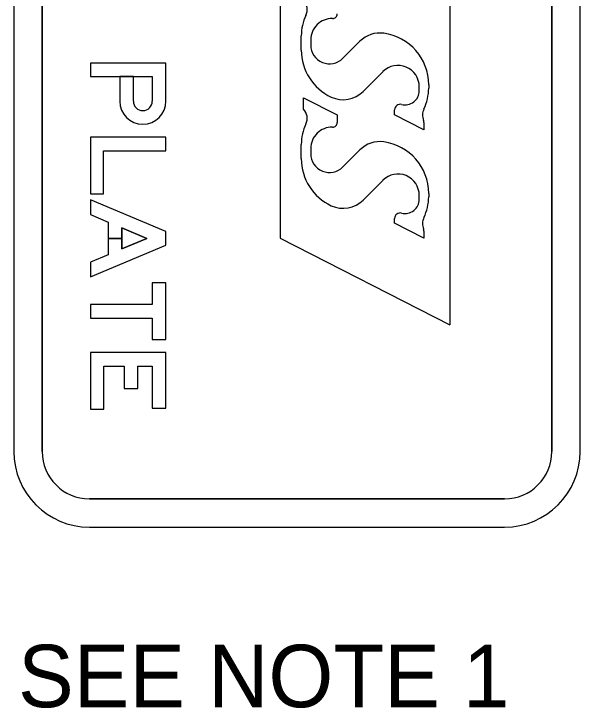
# Model space of a CAD drawing. Extents: x 46672 to 47298, y 5424 to 5829.
# Drawn here: x 46903.28 to 46928.7, y 5543.9 to 5575.02 of the extents above; entities that cross this region are included whole.
import ezdxf

# ---------------------------------------------------------------- set-up
doc = ezdxf.new("R2010")
doc.units = 0
doc.layers.add('SignPanel', color=7, linetype='Continuous')
doc.layers.add('TextLabel', color=7, linetype='Continuous')

msp = doc.modelspace()

# ---------------------------------------------------------------- linework, layer by layer
at = {"layer": 'SignPanel'}
for p, q in [((46903.285, 5609.609), (46903.285, 5555.399)), ((46903.285, 5609.609), (46903.285, 5555.399)), ((46903.285, 5609.596), (46903.285, 5555.399)), ((46903.285, 5609.596), (46903.285, 5555.399)), ((46904.555, 5609.609), (46904.555, 5555.399)), ((46904.555, 5555.399), (46904.555, 5609.596)), ((46904.555, 5555.399), (46904.555, 5609.596)), ((46927.425, 5555.399), (46927.425, 5609.609)), ((46927.425, 5609.609), (46927.425, 5555.399)), ((46927.425, 5609.609), (46927.425, 5555.399)), ((46928.696, 5555.399), (46928.696, 5609.609)), ((46928.696, 5555.399), (46928.696, 5609.609)), ((46928.696, 5555.399), (46928.696, 5609.609)), ((46928.696, 5555.399), (46928.696, 5609.609)), ((46915.23, 5585.803), (46915.23, 5564.971)), ((46922.852, 5585.242), (46922.852, 5561.087)), ((46916.183, 5573.4), (46916.183, 5574.037)), ((46916.606, 5573.857), (46916.606, 5573.628)), ((46918.052, 5573.03), (46918.814, 5573.791)), ((46919.85, 5572.431), (46918.962, 5571.544)), ((46908.038, 5572.208), (46908.038, 5571.107)), ((46909.495, 5572.208), (46909.495, 5571.107)), ((46909.495, 5572.208), (46909.495, 5571.107)), ((46909.495, 5572.208), (46909.495, 5571.107)), ((46921.475, 5571.576), (46921.475, 5571.757)), ((46921.899, 5571.844), (46921.899, 5571.684)), ((46916.289, 5571.26), (46917.798, 5570.492)), ((46916.289, 5570.745), (46916.289, 5571.26)), ((46920.366, 5570.502), (46920.366, 5570.714)), ((46917.798, 5570.492), (46917.798, 5570.151)), ((46921.687, 5569.829), (46920.366, 5570.502)), ((46921.687, 5570.147), (46921.687, 5569.829)), ((46916.183, 5568.531), (46916.183, 5569.169)), ((46916.606, 5568.988), (46916.606, 5568.759)), ((46918.052, 5568.16), (46918.814, 5568.922)), ((46919.85, 5567.561), (46918.962, 5566.674)), ((46921.899, 5566.974), (46921.899, 5566.814)), ((46921.475, 5566.707), (46921.475, 5566.888)), ((46920.366, 5565.633), (46920.366, 5565.845)), ((46921.687, 5564.96), (46920.366, 5565.633)), ((46921.687, 5565.278), (46921.687, 5564.96)), ((46915.23, 5564.971), (46922.852, 5561.087)), ((46906.673, 5553.282), (46925.307, 5553.282)), ((46925.307, 5553.282), (46906.673, 5553.282)), ((46925.307, 5553.282), (46906.673, 5553.282)), ((46906.673, 5552.011), (46925.307, 5552.011)), ((46906.673, 5552.011), (46925.307, 5552.011)), ((46906.673, 5552.011), (46925.307, 5552.011)), ((46906.673, 5552.011), (46925.307, 5552.011))]:
    msp.add_line(p, q, dxfattribs=at)
for points in [[(46910.105, 5571.107), (46910.105, 5572.818), (46906.717, 5572.818), (46906.717, 5572.208), (46908.038, 5572.208)], [(46910.105, 5571.107), (46910.105, 5572.818), (46906.717, 5572.818), (46906.717, 5572.208), (46909.495, 5572.208)], [(46910.105, 5571.107), (46910.105, 5572.818), (46906.717, 5572.818), (46906.717, 5572.208), (46909.495, 5572.208)], [(46908.648, 5571.107), (46908.648, 5572.208), (46908.038, 5572.208), (46908.038, 5571.107)], [(46908.648, 5571.107), (46908.648, 5572.208), (46908.038, 5572.208), (46908.038, 5571.107)], [(46908.648, 5571.107), (46908.648, 5572.208), (46909.495, 5572.208)]]:
    msp.add_lwpolyline(points, dxfattribs=at)
for points in [[(46906.717, 5566.956), (46907.309, 5566.956), (46907.309, 5568.887), (46910.105, 5568.887), (46910.105, 5569.497), (46906.717, 5569.497)], [(46906.717, 5566.956), (46907.309, 5566.956), (46907.309, 5568.887), (46910.105, 5568.887), (46910.105, 5569.497), (46906.717, 5569.497)], [(46906.717, 5566.956), (46907.309, 5566.956), (46907.309, 5568.887), (46910.105, 5568.887), (46910.105, 5569.497), (46906.717, 5569.497)], [(46907.513, 5565.689), (46907.513, 5564.225), (46906.717, 5563.891), (46906.717, 5563.229), (46910.105, 5564.652), (46910.105, 5565.262), (46906.717, 5566.685), (46906.717, 5566.024)], [(46908.123, 5564.481), (46908.123, 5564.957), (46907.513, 5564.957), (46907.513, 5564.225), (46906.717, 5563.891), (46906.717, 5563.229), (46910.105, 5564.652), (46910.105, 5565.262), (46906.717, 5566.685), (46906.717, 5566.024), (46907.513, 5565.689), (46907.513, 5564.957), (46908.123, 5564.957), (46908.123, 5565.433), (46909.256, 5564.957)], [(46908.123, 5564.481), (46908.123, 5564.957), (46907.513, 5564.957), (46907.513, 5564.225), (46906.717, 5563.891), (46906.717, 5563.229), (46910.105, 5564.652), (46910.105, 5565.262), (46906.717, 5566.685), (46906.717, 5566.024), (46907.513, 5565.689), (46907.513, 5564.957), (46908.123, 5564.957), (46908.123, 5565.433), (46909.256, 5564.957)], [(46908.123, 5564.481), (46909.256, 5564.957), (46908.123, 5565.433)], [(46909.495, 5562.958), (46909.495, 5561.993), (46906.717, 5561.993), (46906.717, 5561.383), (46909.495, 5561.383), (46909.495, 5560.417), (46910.105, 5560.417), (46910.105, 5562.958)], [(46909.495, 5562.958), (46909.495, 5561.993), (46906.717, 5561.993), (46906.717, 5561.383), (46909.495, 5561.383), (46909.495, 5560.417), (46910.105, 5560.417), (46910.105, 5562.958)], [(46909.495, 5562.958), (46909.495, 5561.993), (46906.717, 5561.993), (46906.717, 5561.383), (46909.495, 5561.383), (46909.495, 5560.417), (46910.105, 5560.417), (46910.105, 5562.958)], [(46907.326, 5557.3), (46907.326, 5559.231), (46908.238, 5559.231), (46908.238, 5558.232), (46908.848, 5558.232), (46908.848, 5559.231), (46909.495, 5559.231), (46909.495, 5557.351), (46910.105, 5557.351), (46910.105, 5559.841), (46906.717, 5559.841), (46906.717, 5557.3)], [(46907.326, 5557.3), (46907.326, 5559.231), (46908.238, 5559.231), (46908.238, 5558.232), (46908.848, 5558.232), (46908.848, 5559.231), (46909.495, 5559.231), (46909.495, 5557.351), (46910.105, 5557.351), (46910.105, 5559.841), (46906.717, 5559.841), (46906.717, 5557.3)], [(46907.326, 5557.3), (46907.326, 5559.231), (46908.238, 5559.231), (46908.238, 5558.232), (46908.848, 5558.232), (46908.848, 5559.231), (46909.495, 5559.231), (46909.495, 5557.351), (46910.105, 5557.351), (46910.105, 5559.841), (46906.717, 5559.841), (46906.717, 5557.3)]]:
    msp.add_lwpolyline(points, close=True, dxfattribs=at)
for centre, radius, start, end in [((46915.856, 5575.21), 0.593, 334.3795, 43.1892), ((46918.3, 5574.038), 2.117, 154.3795, 180), ((46917.559, 5573.857), 0.953, 88.6664, 180), ((46917.586, 5575.021), 0.212, 268.6664, 360), ((46919.712, 5572.893), 1.27, 82.3089, 135), ((46919.57, 5571.844), 2.329, 360, 82.3089), ((46917.453, 5573.629), 0.847, 180, 315), ((46918.511, 5573.401), 2.329, 180, 244.95), ((46920.523, 5571.758), 0.953, 360, 135), ((46919.782, 5571.684), 2.117, 334.0896, 360), ((46918.063, 5572.442), 1.27, 244.95, 315), ((46920.84, 5571.576), 0.635, 255.6915, 360), ((46915.856, 5570.34), 0.593, 334.3795, 43.1892), ((46920.621, 5570.714), 0.254, 75.6915, 180), ((46922.257, 5570.481), 0.635, 154.0896, 202.0347), ((46918.3, 5569.169), 2.117, 154.3795, 180), ((46917.586, 5570.152), 0.212, 268.6664, 360), ((46921.433, 5570.147), 0.254, 360, 22.0347), ((46917.559, 5568.988), 0.953, 88.6664, 180), ((46919.712, 5568.024), 1.27, 82.3089, 135), ((46919.57, 5566.975), 2.329, 360, 82.3089), ((46918.511, 5568.532), 2.329, 180, 244.95), ((46917.453, 5568.759), 0.847, 180, 315), ((46920.523, 5566.888), 0.953, 360, 135), ((46918.063, 5567.573), 1.27, 244.95, 315), ((46920.84, 5566.707), 0.635, 255.6915, 360), ((46919.782, 5566.814), 2.117, 334.0896, 360), ((46920.621, 5565.845), 0.254, 75.6915, 180), ((46922.257, 5565.612), 0.635, 154.0896, 202.0347), ((46921.433, 5565.278), 0.254, 360, 22.0347), ((46906.673, 5555.399), 3.388, 180, 270), ((46906.673, 5555.399), 3.388, 180, 270), ((46906.673, 5555.399), 3.388, 180, 270), ((46906.673, 5555.399), 3.388, 180, 270), ((46906.673, 5555.399), 2.118, 180, 270), ((46906.673, 5555.399), 2.118, 180, 270), ((46906.673, 5555.399), 2.118, 180, 270), ((46925.307, 5555.399), 3.388, 270, 360), ((46925.307, 5555.399), 3.388, 270, 360), ((46925.307, 5555.399), 2.118, 270, 360), ((46925.307, 5555.399), 3.388, 270, 360), ((46925.307, 5555.399), 2.118, 270, 360), ((46925.307, 5555.399), 3.388, 270, 360), ((46925.307, 5555.399), 2.118, 270, 360)]:
    msp.add_arc(centre, radius, start, end, dxfattribs=at)
for major_axis in [(1.033, 0), (1.033, 0), (1.033, 0), (0.424, 0), (0.424, 0), (0.424, 0)]:
    msp.add_ellipse((46909.071, 5571.107), major_axis=major_axis, ratio=0.999994, start_param=3.141593, end_param=6.283185, dxfattribs=at)

# ---------------------------------------------------------------- texts
at = {"layer": 'TextLabel'}
msp.add_text('SEE NOTE 1', height=2.8, dxfattribs=at).set_placement((46903.472, 5543.936))

doc.saveas('drawing.dxf')
